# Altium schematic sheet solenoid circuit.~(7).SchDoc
size A; SheetNumber: 1; SheetTotal: 1
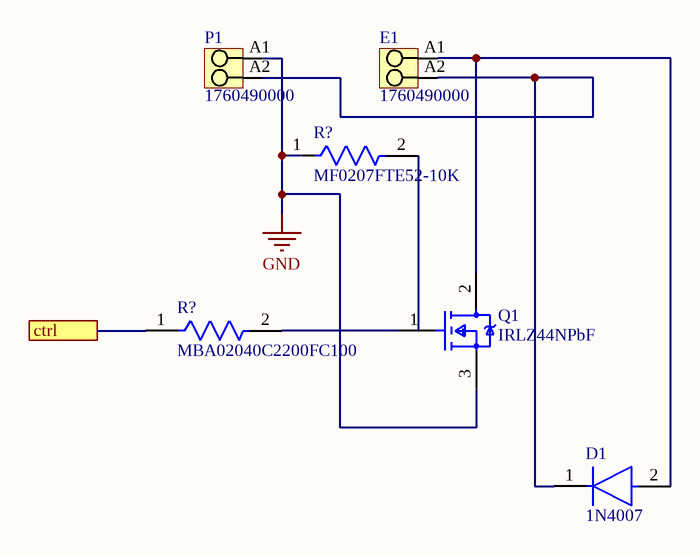
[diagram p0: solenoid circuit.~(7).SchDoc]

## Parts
(Parts that share a designator on the sheet are numbered #1, #2 ... from top to bottom, then left to right.)
D1  1N4007  [FP-1N4007-MFG]
E1  1760490000  [PM_5_08_90_02]
P1  1760490000  [PM_5_08_90_02]
Q1  IRLZ44NPbF  [FP-PG-TO220-3-MFG]
R?#1  MF0207FTE52-10K  [FP-MF0207-MFG]
R?#2  MBA02040C2200FC100  [FP-MBA0204-MFG]

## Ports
ctrl

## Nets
GND: P1.A1 Q1.3(S) R?#1.1
ctrl: R?#2.1 ; port ctrl
NetD1_1: D1.1(C) E1.A2 P1.A2
NetD1_2: D1.2(A) E1.A1 Q1.2(D)
NetQ1_1: Q1.1(G) R?#2.2

Not connected (* = marked no-connect by the designer): R?#1 2

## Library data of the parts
D1 = CMP-123542-000001-1: Rectifier diode 1000 V 1 A DO-41, ,; Manufacturer: Diotec; Max Surge Forward Current: 27A; Forward Current: 1A; Max Junction Temp: +175°C; Reverse Voltage: 1000V; Value: 15pF; Peak Reverse Current: 5uA
E1 P1 = CMP-1559-01627-1: OMNIMATE Signal - series PM; Manufacturer: Weidmueller; Contact_surface: tinned; Pitch_mm: 5,08 mm; Solid_min_H05_07_V_U: 0,13 mm²; Wire_cross_section_AWG_min_UL_1059: AWG 26; Wire_cross_section_AWG_max_UL_1059: AWG 14; Rated_voltage_for_surge_voltage_class_pollution_degree_II_2: 600 V; Rated_current_use_group_B_UL_1059: 15 A; Mounting_onto_the_PCB: Solder connection; Solder_pin_length_mm: 3,5 mm; Side_termination_characteristic: closed side; Contact_material: Cu-Leg; Pitch_inch: 0,2 inch; No_of_poles: 2; UL_94_flammability_rating: V-0; Insulating_material: Wemid (PA); Rated_voltage_use_group_B_UL_1059: 300 V; Solid_max_H05_07_V_U: 2,5 mm²; Short_text_for_material: PM 5.08/02/90 3.5SN OR BX
Q1 = CMP-32901-000488-1: MOSFET N-CH 55V 47A TO220AB; Turn-On Delay Time: 11ns; Gate to Source Voltage (Vgs): 16V; Element Configuration: Single; Rds On Max: 22mR; Turn-Off Delay Time: 26ns; Max Power Dissipation: 110W; Threshold Voltage: 2V; Drain to Source Resistance: 35mR; Input Capacitance: 1.7nF
R?#1 = CMP-03413-000006-1: RES 10K OHM 1% 0.6W AXIAL; Temperature Coefficient: 50ppm/°C; Resistance: 10kR
R?#2 = CMP-02408-000005-1: RES 220 OHM 0.4W 1% AXIAL; Manufacturer: Vishay BC Components; Automotive Grade: Grade 1; Value: 220Ω; Voltage Rating: 200V; Temperature Coefficient: 50ppm/°C; Power Rating: 0.25W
